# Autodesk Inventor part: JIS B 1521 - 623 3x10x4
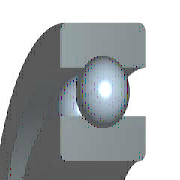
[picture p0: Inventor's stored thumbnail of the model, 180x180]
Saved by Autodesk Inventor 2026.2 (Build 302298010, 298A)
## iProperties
Created: 2025-01
Part Number: JIS B 1521 - 623 3x10x4
Material: 강철, 연강
Description: 깊은 그루부 볼 베어링
Document SubType Name: Modeling
Standard: JIS B 1521
Designer: work
Standard Revision: 2012
Standards Organization: JIS
Language: ko-KR
Size Designation: 623 3x10x4
Categories: <MemberInstance><Categories><Category DisplayName="샤프트 부품" InternalName="7f7aeb1f-a693-4053-b835-cee3144e0d98" Mnemonic="SHFT"><Category DisplayName="베어링" Inter
Density: 7.85 g/cm^3
Appearance: 반연마
IsCustomPart: 1
Author: work
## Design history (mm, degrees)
revolve "본체" stored, may be unused: angle "d6" = 90 deg
revolve "볼" stored, may be unused: angle "d7" = 90 deg
pattern_circular "IDS_ARRAYBALL[SIMPL:T]" dims angle "d3" = 360 deg
body "Solid1"
sketch "스케치" dims "d0" = 1.82 (= -0.26 x WD + 0.26 x BD)
  geometry: L1 (1.09, 3.25)-(2.91, 3.25); L2 (2, 3.25)-(2, 2.34); L3 (2, 3.25)-(2, 4.16); L4 (1.324, 2.641)-(0, 2.641); L5 (0, 1.5)-(4, 1.5); L6 (1.324, 3.859)-(0, 3.859); L7 (0, 5)-(4, 5); L8 (4, 1.5)-(4, 2.641); L9 (2.676, 2.641)-(4, 2.641); L10 (2.676, 3.859)-(4, 3.859); L11 (4, 5)-(4, 3.859); L12 (-1.4, 0)-(8.4, 0) reference; L13 (0, -0.3)-(0, 5.3) reference
  constraints: 22 end point, 4 point on line, 2 collinear, 2 perpendicular, 2 symmetric about line, 1 midpoint, 1 parallel, 14 other
  dimensions: "d9" = 3 diameter of L5 L12 (= WD); "d11" = 10 diameter of L7 L12 (= BD); "d12" = 4 distance between parallel lines of L8 L13 (= KB); "d13" = 5.282 diameter of L9 L12 (= 0.326 x BD + 0.674 x WD)
fillet "모깎기1" dims "d1" = 0.15 (= KRS)
other parameters: "WD" = 3 [user parameter; used in 5 equation terms], "BD" = 10 [user parameter; used in 5 equation terms], "KB" = 4 [user parameter; used in 1 equation term], "KRS" = 0.15 [user parameter; used in 1 equation term], "d4" = 0, "d5" = 0, "d8" = 0, "d14" = 0, "d15" = 0, "BBA" = 0 [user parameter], "BC0" = 218000 [user parameter], "BC" = 630000 [user parameter], "BR" = 5 (= 0.5 x BD) [user parameter], "WR" = 1.5 (= 0.5 x WD) [user parameter]
